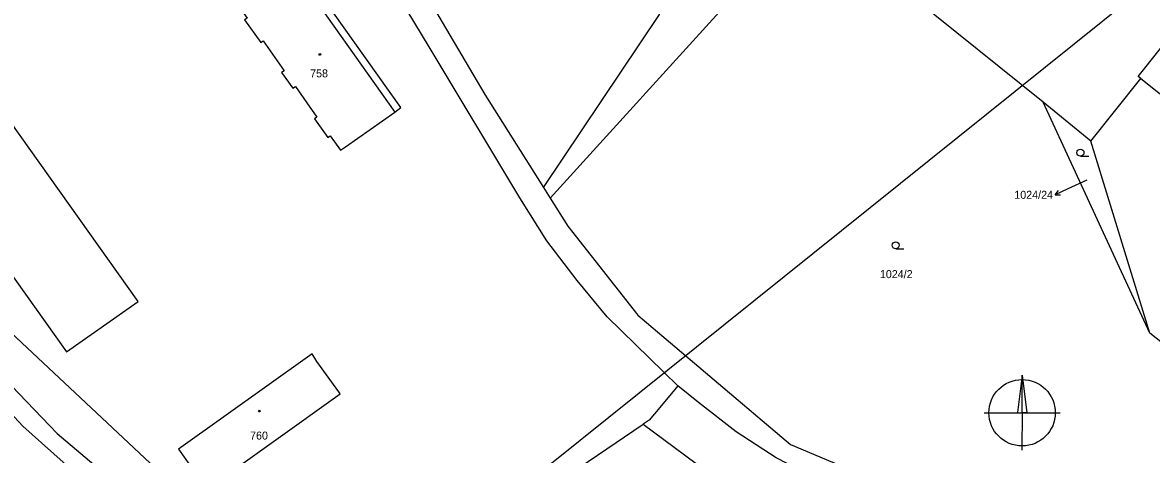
# Model space of a CAD drawing. Extents: x -793666 to -785424, y -1118958 to -1108761.
# Drawn here: x -792584 to -792344.1, y -1109782.8 to -1109691.1 of the extents above; entities that cross this region are included whole.
import ezdxf

# ---------------------------------------------------------------- set-up
doc = ezdxf.new("R2010")
doc.units = 0
for name, color, linetype in [('1_2000 - úřady', 7, 'Continuous'), ('Hranice parcel', 7, 'Continuous'), ('Parcelní čísla', 7, 'Continuous'), ('Pop  PČ popisy', 7, 'Continuous'), ('Vnitřní kresba', 7, 'Continuous'), ('Značky budov', 7, 'Continuous'), ('Značky kultur', 7, 'Continuous')]:
    doc.layers.add(name, color=color, linetype=linetype)

msp = doc.modelspace()

# ---------------------------------------------------------------- linework, layer by layer
at = {"layer": '1_2000 - úřady'}
for p, q in [((-792371.54, -1109765.97), (-792372.53, -1109773.9)), ((-792379.62, -1109773.93), (-792363.49, -1109773.96)), ((-792371.56, -1109773.93), (-792371.59, -1109781.9))]:
    msp.add_line(p, q, dxfattribs=at)
for points in [[(-791938.08, -1109742.36), (-792598.01, -1110271.46), (-792786.15, -1110036.8), (-792126.22, -1109507.7)], [(-792371.54, -1109765.97), (-792370.57, -1109773.93), (-792371.56, -1109773.93)]]:
    msp.add_lwpolyline(points, close=True, dxfattribs=at)
msp.add_circle((-792371.56, -1109773.93), 7.05, dxfattribs=at)
at = {"layer": 'Hranice parcel'}
for p, q in [((-792367.12, -1109708.02), (-792416.25, -1109668.41)), ((-792428.17, -1109680.34), (-792471.85, -1109728.39)), ((-792356.93, -1109716.24), (-792346.37, -1109702.94)), ((-792344.46, -1109757.04), (-792367.12, -1109708.02)), ((-792356.93, -1109716.24), (-792367.12, -1109708.02)), ((-792344.46, -1109757.04), (-792356.93, -1109716.24)), ((-792473.29, -1109726.11), (-792471.85, -1109728.39)), ((-792444.74, -1109768.18), (-792459.77, -1109753.58)), ((-792293.96, -1109796.98), (-792344.46, -1109757.04)), ((-792483.31, -1109797.44), (-792452.06, -1109776.34))]:
    msp.add_line(p, q, dxfattribs=at)
for points in [[(-792544.19, -1109531.17), (-792531.93, -1109568.54), (-792528.55, -1109587.33), (-792527.38, -1109597.88), (-792527.06, -1109604.47), (-792525.2, -1109617.17), (-792519.4, -1109641.05), (-792509.1, -1109663.72), (-792498.02, -1109685.41), (-792485.75, -1109706.33), (-792473.29, -1109726.11)], [(-792459.77, -1109753.58), (-792466.13, -1109745.86), (-792472.55, -1109737.39), (-792478.3, -1109728.3), (-792497.34, -1109696.59), (-792502.47, -1109688.17), (-792513.98, -1109665.8), (-792523, -1109645.03), (-792526.52, -1109636.29), (-792529.23, -1109620.4), (-792529.08, -1109619.26), (-792534.29, -1109590.34), (-792536.2, -1109577.37), (-792539.25, -1109572.49), (-792536.68, -1109571.58), (-792542.26, -1109556.12)], [(-792718.74, -1109582.83), (-792684.62, -1109620.8), (-792673.86, -1109638.49), (-792648.83, -1109676.6), (-792595.57, -1109748.42), (-792548.94, -1109792.07), (-792510.02, -1109815.62)], [(-792346.37, -1109702.94), (-792346.88, -1109702.53), (-792297.84, -1109640.99), (-792294.9, -1109643.34)], [(-792674.34, -1109647.36), (-792651.82, -1109684.77), (-792621.5, -1109724.44), (-792592.84, -1109761.47), (-792576.63, -1109778.3), (-792563.81, -1109789.18), (-792557.58, -1109793.43), (-792536.65, -1109804.52)], [(-792473.29, -1109726.11), (-792448.59, -1109689.37), (-792442.6, -1109660.54)], [(-792538.8, -1109687.82), (-792538.2, -1109687.4), (-792536.26, -1109690.14), (-792536.78, -1109690.5), (-792533.36, -1109695.35), (-792532.84, -1109694.98), (-792528.38, -1109701.3), (-792528.9, -1109701.67), (-792526.51, -1109705.04), (-792525.99, -1109704.67), (-792523.53, -1109708.12), (-792521.4, -1109711.17), (-792521.92, -1109711.54), (-792519.11, -1109715.52), (-792518.59, -1109715.15), (-792516.42, -1109718.21), (-792515.32, -1109717.44), (-792504.87, -1109710.08), (-792503.56, -1109709.15), (-792525.41, -1109678.37), (-792526.73, -1109679.3), (-792533.28, -1109670.03)], [(-792618.15, -1109694.73), (-792607.44, -1109709.76), (-792609.88, -1109711.5), (-792574.61, -1109760.98), (-792559.4, -1109750.29), (-792605.41, -1109685.63), (-792618.15, -1109694.73)], [(-792346.37, -1109702.94), (-792332.79, -1109713.75), (-792340.26, -1109723.13), (-792326.19, -1109734.34), (-792333.66, -1109743.71), (-792319.04, -1109755.37), (-792315.33, -1109750.72)], [(-792471.85, -1109728.39), (-792468.12, -1109734.31), (-792453.21, -1109753.19)], [(-792573.36, -1109786.15), (-792583.89, -1109776.79), (-792597.47, -1109762.19), (-792609.81, -1109746.62), (-792615.6, -1109738.9)], [(-792453.21, -1109753.19), (-792420.77, -1109780.63), (-792378.22, -1109798.57), (-792379.5, -1109803.55)], [(-792522.44, -1109761.43), (-792550.85, -1109781.64), (-792544.82, -1109790.11), (-792516.44, -1109769.89), (-792516.73, -1109769.48), (-792521.41, -1109763.02), (-792522.44, -1109761.43)], [(-792444.74, -1109768.18), (-792448.57, -1109772.79), (-792450.82, -1109775.5), (-792452.06, -1109776.34)], [(-792388.57, -1109800.3), (-792400.89, -1109795.29), (-792423.79, -1109783.49), (-792432.31, -1109777.95), (-792440.35, -1109771.76), (-792444.74, -1109768.18)], [(-792452.06, -1109776.34), (-792436.41, -1109787.92), (-792426.99, -1109794.1)]]:
    msp.add_lwpolyline(points, dxfattribs=at)
at = {"layer": 'Pop  PČ popisy'}
for p, q in [((-792357.84, -1109724.52), (-792361.82, -1109726.38)), ((-792361.82, -1109726.38), (-792364.54, -1109727.65)), ((-792364.54, -1109727.65), (-792363.84, -1109726.77)), ((-792364.54, -1109727.65), (-792363.42, -1109727.68))]:
    msp.add_line(p, q, dxfattribs=at)
at = {"layer": 'Vnitřní kresba'}
msp.add_line((-792526.73, -1109679.3), (-792504.87, -1109710.08), dxfattribs=at)
at = {"layer": 'Značky budov'}
for centre in [(-792520.78, -1109697.85), (-792533.65, -1109773.57)]:
    msp.add_circle(centre, 0.175, dxfattribs=at)
at = {"layer": 'Značky kultur'}
for p, q in [((-792359.17, -1109719.45), (-792357.42, -1109719.45)), ((-792398.42, -1109739.12), (-792396.67, -1109739.12))]:
    msp.add_line(p, q, dxfattribs=at)
for centre in [(-792359.17, -1109718.7), (-792398.42, -1109738.37)]:
    msp.add_circle(centre, 0.75, dxfattribs=at)

# ---------------------------------------------------------------- texts
at = {"layer": 'Parcelní čísla'}
for s, p in [('758', (-792522.85, -1109702.72)), ('1024/24', (-792373.22, -1109728.5)), ('1024/2', (-792401.79, -1109745.34)), ('760', (-792535.61, -1109779.62))]:
    msp.add_text(s, height=1.7, dxfattribs=at).set_placement(p)

doc.saveas('drawing.dxf')
